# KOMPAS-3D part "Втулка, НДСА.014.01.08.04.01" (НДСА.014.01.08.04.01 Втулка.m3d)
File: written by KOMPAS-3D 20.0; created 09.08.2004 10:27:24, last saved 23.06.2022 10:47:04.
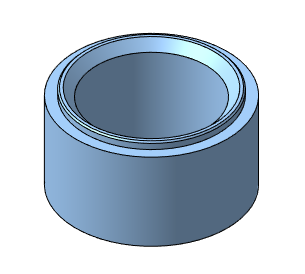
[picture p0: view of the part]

Document properties: Автор: Устинов А.В.; Организация: Эсто-вакуум; Полное имя файла: C:\Users\cherbakova\Desktop\PLM\НДСА.014.01.08.04.01 Втулка.m3d

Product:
- Part/product: Втулка  | designation НДСА.014.01.08.04.01
    Материал: Сталь 20 ГОСТ 1050-88 (density 7859 kg/m3)
    Масса: 2.30705
    additional columns: <item xmlns="http://appius.ru/pdm" xmlns:xs="http://www.w3.org/2001/XMLSchema" x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; <item xmlns="http://appius.ru/pdm" xmlns:xs="http://www.w3.org/2001/XMLSchema" x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; <item xmlns="http://appius.ru/pdm" xmlns:xs="http://www.w3.org/2001/XMLSchema" x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; <item xmlns="http://appius.ru/pdm" xmlns:xs="http://www.w3.org/2001/XMLSchema" x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; <item xmlns="http://appius.ru/pdm" xmlns:xs="http://www.w3.org/2001/XMLSchema" x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; <item xmlns="http://appius.ru/pdm" xmlns:xs="http://www.w3.org/2001/XMLSchema" x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
    source file: НДСА.014.01.08.04.01 Втулка.CDW

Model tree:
1. Плоскость XY
2. Плоскость ZX
3. Плоскость ZY
4. Начало координат
5. Эскиз:1
6. Операция выдавливания:1
     Расстояние 1 = 63
7. Эскиз:2  (labels: Операция выдавливания:1; Операция выдавливания:1)
8. Вырезать элемент выдавливания:1
     Расстояние 2 = 5
9. Фаска:2  (labels: Вырезать элемент выдавливания:1)
     Угол = 45; Длина 1 = 1; Длина 2 = 1
10. Эскиз:10  (labels: Операция выдавливания:1)
11. Вырезать элемент выдавливания:9  (labels: Сталь 20 ГОСТ 1050-88)
     Расстояние 2 = 6; Угол 2 = 45

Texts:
  НДСА.014.01.08.04.01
